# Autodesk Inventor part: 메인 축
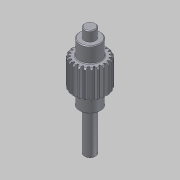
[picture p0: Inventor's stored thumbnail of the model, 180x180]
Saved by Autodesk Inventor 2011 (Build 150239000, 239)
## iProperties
Created: 2014-07
Part Number: 메인 축
Material: Steel
Document SubType Name: Modeling
Designer: KYOUNG IL JANG
Categories: <?xml version="1.0" encoding="UTF-16"?> <MemberInstance><Categories><FamilyTemplate><FamilyTemplateParameter ValueType="xs:double" Id="1" ObjectReferenceKey="da
Density: 1 g/cm^3
CustomPartVersion: 1
Company: 한국ATC센터
Author: KYOUNG IL JANG
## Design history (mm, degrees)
sketch "Sketch1"
  geometry: C1 r 12 at (0, 0)
  constraints: 1 centre point
  dimensions: "d0" = 24 diameter of C1 (= da_da)
extrude "Extrusion1" new body sketch "Sketch1" distance "d1" = 20 (= da_b); taper "d2" = 0 deg
workplane "Work Plane2"
sketch "Sketch2"
  geometry: C1 r 12 at (0, 0) reference; C2 r 11 at (0, 0)
  constraints: 1 centre point, 1 coincident
  dimensions: "d3" = 22 diameter of C2 (= da_dw)
feature "피치 지름" sketch "Sketch2" dims "d4" = 10, "d5" = 0
workplane "Work Plane8"
workplane "Work Plane9"
chamfer "모따기1" distance "d49" = 1; stored, may be unused: second distance "d50" = 2, angle "d51" = 45 deg
sketch "스케치3"
  geometry: C1 r 7.5 at (0, 0); 1 further point
  constraints: 1 centre point, 1 coincident
  dimensions: "d52" = 15 diameter of C1
extrude "돌출2" join sketch "스케치3" distance "d53" = 11; taper "d54" = 0 deg
sketch "스케치4"
  geometry: C1 r 4 at (0, 0); 1 further point
  constraints: 1 centre point, 1 coincident
  dimensions: "d55" = 8 diameter of C1
extrude "돌출3" join sketch "스케치4" distance "d56" = 7; taper "d57" = 0 deg
sketch "스케치5"
  geometry: C1 r 7.5 at (0, 0) reference; C2 r 7.5 at (0, 0) reference; 1 further point
extrude "돌출4" join sketch "스케치5" distance "d62" = 11; taper "d63" = 0 deg
sketch "스케치6"
  geometry: C1 r 4 at (0, 0); 1 further point
  constraints: 1 centre point, 1 coincident
  dimensions: "d64" = 8 diameter of C1
extrude "돌출5" join sketch "스케치6" distance "d65" = 30; taper "d66" = 0 deg
chamfer "모따기2" distance "d58" = 0.5; stored, may be unused: second distance "d59" = 2, angle "d60" = 45 deg
fillet "모깎기1" dims "d61" = 0.5
feature "스퍼 기어" dims "da_b" = 20, "da_d" = 22, "da_aw" = 31, "da_da" = 24, "da_df" = 19.5, "da_dw" = 22, angle "da_beta" = 0 deg, "da_lefttooth" = 0, "da_righttooth" = 0
body "Solid1"
body "Srf1"
node "투영된 루프1"
other parameters: "d16" = 31 (= da_aw), "d17" = 0, "d34" = 1.428 (computed from da_z), "d39" = 0, "d41" = 0, "d43" = 31 (= da_aw), "d46" = 31 (= da_aw), "d47" = 0, "d48" = 0
